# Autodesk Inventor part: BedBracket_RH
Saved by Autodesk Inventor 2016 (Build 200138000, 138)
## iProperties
Created: 2016-01
Part Number: BedBracket_RH
Material: Generic
Document SubType Name: Modeling
Designer: John
Density: 1 g/cm^3
Appearance: Default
Author: John
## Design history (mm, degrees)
feature "Base1"
body "Solid1"
